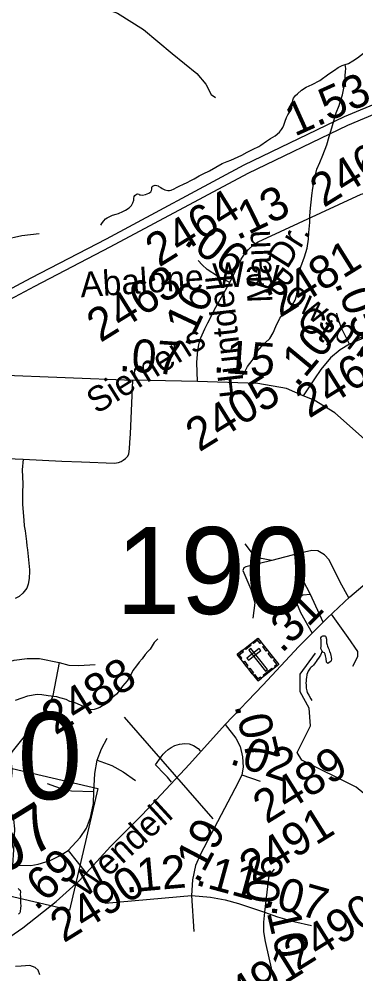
# Model space of a CAD drawing. Extents: x 2001466 to 31450019, y -30647475 to 847247.
# Drawn here: x 2179202 to 2181740, y 748208 to 755417 of the extents above; entities that cross this region are included whole.
import ezdxf

# ---------------------------------------------------------------- set-up
doc = ezdxf.new("R2010")
doc.units = 0
for name, color, linetype in [('Exist Cultural Cemetery CELL', 7, 'Continuous'), ('Exist Hydrographic Creek Single Shore', 7, 'Continuous'), ('Exist Hydrographic Misc Water Feature', 7, 'Continuous'), ('Exist Road Non-System Type 51', 7, 'Continuous'), ('Exist Road Primary NC Attributed', 7, 'Continuous'), ('Exist Road Primary NC Label', 7, 'Continuous'), ('Exist Road Primary NC Service Mileage Hundredths English Label', 7, 'Continuous'), ('Exist Road Primary NC Shield CELL', 7, 'Continuous'), ('Exist Road Primary NC Shield Number Label', 7, 'Continuous'), ('Exist Road Primary US Divided Attributed', 7, 'Continuous'), ('Exist Road Primary US Mileage Hundredths English Label', 7, 'Continuous'), ('Exist Road Secondary Mileage Hundredths English Label', 7, 'Continuous'), ('Exist Road Secondary Structure Standard Bridge Number Label', 7, 'Continuous'), ('Exist Road Secondary Type 51 Attributed', 7, 'Continuous'), ('Exist Road Secondary Type 51 Label', 7, 'Continuous'), ('Exist Road Secondary Type 51 Number Label', 7, 'Continuous')]:
    doc.layers.add(name, color=color, linetype=linetype)

msp = doc.modelspace()

# ---------------------------------------------------------------- linework, layer by layer
at = {"layer": 'Exist Cultural Cemetery CELL'}
for points in [[(2180845.5, 750619.4), (2181001.7, 750742.8), (2181159.5, 750543), (2181003.3, 750419.5)], [(2180903.6, 750665.2), (2180944.3, 750697.4), (2180951.3, 750688.4), (2180910.7, 750656.3)], [(2181028.6, 750708.8), (2181019.7, 750701.7), (2180999.8, 750727), (2180967.9, 750701.9), (2180961, 750710.6), (2181001.8, 750742.8)], [(2181065, 750644.4), (2181038.1, 750678.3), (2181047.1, 750685.4), (2181073.9, 750651.4)], [(2180872.3, 750585.4), (2180881.2, 750592.4), (2180861.3, 750617.7), (2180893.1, 750642.8), (2180886.2, 750651.5), (2180845.5, 750619.4)], [(2180919.7, 750591.2), (2180931.3, 750576.6), (2181023.7, 750649.6), (2181012.1, 750664.2)], [(2180949.2, 750663.9), (2180934.5, 750652.4), (2181060.2, 750493.2), (2181074.9, 750504.8)], [(2181105.8, 750592.6), (2181079, 750626.6), (2181087.9, 750633.7), (2181114.8, 750599.7)], [(2180918.3, 750527.2), (2180891.4, 750561.1), (2180900.4, 750568.2), (2180927.2, 750534.2)], [(2181133.5, 750522.4), (2181126.4, 750531.4), (2181143.7, 750545.1), (2181118.6, 750576.8), (2181127.4, 750583.7), (2181159.5, 750543)], [(2180959.9, 750474.4), (2180933.1, 750508.4), (2180942, 750515.4), (2180968.9, 750481.5)], [(2181029.2, 750440.1), (2181022.1, 750449.1), (2181004.9, 750435.5), (2180979.8, 750467.2), (2180971.1, 750460.3), (2181003.2, 750419.5)], [(2181041.3, 750464.2), (2181107.9, 750516.8), (2181114.9, 750507.8), (2181048.4, 750455.2)]]:
    msp.add_lwpolyline(points, close=True, dxfattribs=at)
at = {"layer": 'Exist Hydrographic Creek Single Shore'}
msp.add_lwpolyline([(2183862.9, 748759.6), (2183595.9, 748784.7), (2183229.9, 748723.3), (2182980, 748715.3), (2182755, 748756.1), (2182328.9, 748994.5), (2182043.1, 749367.7), (2181742.1, 749616.6), (2181333, 749821.8), (2181299, 749878.2), (2181398, 750079.6), (2181389, 750214.3), (2181321.1, 750337.1), (2181321.1, 750471.6), (2181435.9, 750630)], dxfattribs=at)
at = {"layer": 'Exist Hydrographic Misc Water Feature'}
for points in [[(2181660.3, 755073.2), (2181684, 755081.4), (2181718.1, 755101.4), (2181751.9, 755123.9), (2181821.4, 755176.3), (2181888.9, 755234.6), (2181924.6, 755272.6), (2181948.6, 755306.7), (2181970.5, 755337.1), (2181980.5, 755351)], [(2180869.4, 752707.8), (2180895.2, 752737.9), (2180924.9, 752793.9), (2180958.8, 752838.3), (2180974.4, 752866.3), (2180996.5, 752906.4), (2181046.1, 752964.6), (2181052.3, 752968.5), (2181055.8, 752972.4), (2181091.8, 753004.7), (2181117.5, 753046.7), (2181137.4, 753096.8), (2181166.9, 753157.3), (2181190.5, 753189.4), (2181218.8, 753213.5), (2181248.3, 753237.5), (2181266.1, 753263.5), (2181284, 753293.7), (2181294, 753327.9), (2181297.7, 753355.7), (2181303.5, 753406), (2181307.4, 753443.9), (2181313.3, 753497.8), (2181326.8, 753546.1), (2181354.3, 753622.2), (2181374, 753688.2), (2181383.4, 753756.1), (2181387.1, 753806.3), (2181392.7, 753880.1), (2181394.7, 753930.1), (2181398.2, 753990), (2181405.8, 754056.2), (2181407.6, 754084.3), (2181415.2, 754140.3), (2181429, 754210.1), (2181446.6, 754282.4), (2181468.3, 754334.3), (2181491.7, 754390.5), (2181521.4, 754466.7), (2181539.3, 754530.9), (2181559, 754594.9), (2181580.3, 754665.1), (2181592, 754709.2), (2181613.7, 754763), (2181625.6, 754799), (2181639.1, 754845.2), (2181652.9, 754907.2), (2181658.6, 754949.3), (2181660.5, 754991.3), (2181662.3, 755019.4), (2181664.6, 755043.4), (2181660.3, 755073.2)], [(2181277.4, 754829.3), (2181285.6, 754839.4), (2181301, 754853.3), (2181331.3, 754879.6), (2181366.8, 754901.8), (2181411.1, 754921.9), (2181468.7, 754954.1), (2181536.6, 755002.7), (2181580.5, 755030.9), (2181608, 755051.1), (2181638.1, 755065.2), (2181660.3, 755073.2)], [(2179819.5, 753859.5), (2179825, 753873.2), (2179831.2, 753881.3), (2179841.2, 753893.5), (2179853.3, 753907.5), (2179864.8, 753915.5), (2179881, 753923.6), (2179906.9, 753935.9), (2179932.9, 753943.8), (2179950.9, 753950), (2179984.8, 753964.3), (2180004.7, 753974.3), (2180032.3, 753992.4), (2180048.5, 754008.6), (2180058.6, 754030.6), (2180066.4, 754048.5), (2180068.2, 754062.8), (2180070.3, 754076.7), (2180074, 754084.7), (2180088.1, 754094.7), (2180093.9, 754096.7), (2180104.1, 754094.7), (2180109.9, 754091), (2180116, 754088.9), (2180131.8, 754086.9), (2180155.8, 754093), (2180180, 754103.1), (2180193.9, 754113.2), (2180199.9, 754123.2), (2180201.7, 754131.5), (2180201.7, 754147.3), (2180205.8, 754153.2), (2180212, 754157.5), (2180219.6, 754159.2), (2180227.6, 754161.7), (2180239.4, 754159.5), (2180249.3, 754157.6), (2180256.1, 754153.7), (2180269.6, 754143.9), (2180281.7, 754137.6), (2180301.8, 754128.1), (2180322.1, 754121.8), (2180335.6, 754122.2), (2180347.5, 754124), (2180370.1, 754134.5), (2180389.5, 754144.4), (2180413.7, 754156.6), (2180437.3, 754168.9), (2180473.6, 754184.9), (2180491, 754194.8), (2180521.4, 754210.9), (2180559.1, 754233.2), (2180588.9, 754249.4), (2180636.8, 754271.8), (2180684.8, 754299.8), (2180732.6, 754326.3), (2180770.5, 754342.4), (2180798.2, 754352.5), (2180882.1, 754388.9), (2180921.9, 754411.3), (2180965.7, 754435.4), (2181010, 754455.9), (2181023.8, 754464), (2181067.2, 754496), (2181097.2, 754514.2), (2181133.1, 754536.3), (2181165.1, 754562.7), (2181181, 754582.6), (2181190.7, 754598.6), (2181196.6, 754614.7), (2181208.5, 754647), (2181218.8, 754673.1), (2181228.4, 754693.1), (2181232.3, 754701), (2181249.7, 754727.2), (2181257.9, 754745), (2181259.8, 754769.1), (2181261.8, 754789), (2181265.3, 754805.1), (2181271.5, 754819.2), (2181277.4, 754829.3)], [(2181487, 750643.7), (2181476.7, 750663.5), (2181478.8, 750681.5), (2181478.8, 750695.7), (2181478.6, 750707.9), (2181478.4, 750729.8), (2181476.3, 750737.9), (2181476.5, 750741.5), (2181476.3, 750745.6), (2181480.2, 750753.5), (2181486.2, 750757.9), (2181490.3, 750759.7), (2181496.2, 750759.6), (2181500.3, 750759.8), (2181506.3, 750759.7), (2181510.4, 750757.9), (2181514.5, 750752), (2181518.6, 750735.9), (2181520.2, 750725.9), (2181520.2, 750708.1), (2181524.9, 750692), (2181527, 750681.9), (2181530.5, 750670), (2181532.9, 750664), (2181538.5, 750654.2), (2181540.9, 750640.1), (2181547.1, 750633.9), (2181551, 750612.2), (2181553.2, 750602.1), (2181555.3, 750596.1), (2181557.3, 750584), (2181555.3, 750574.2), (2181551.2, 750566.3), (2181539.5, 750557.9), (2181529.2, 750550.1), (2181523.5, 750555.9), (2181519.8, 750561.7), (2181515.5, 750590), (2181510.8, 750608.1), (2181508.9, 750621.8), (2181503, 750632), (2181491.1, 750637.9), (2181487, 750643.7)], [(2180246.6, 750736.7), (2180220.8, 750708.5), (2180205.4, 750684.6), (2180189.4, 750660.6), (2180173.2, 750642.4), (2180151.3, 750618.1), (2180129.7, 750586), (2180108, 750560.1), (2180085.9, 750533.8), (2180060.2, 750499.6), (2180040.8, 750461.6), (2180016.8, 750419.4), (2179982.7, 750379.4), (2179951.6, 750337.1), (2179935.4, 750320.9), (2179907.5, 750296.7), (2179883.7, 750268.7), (2179867.7, 750256.9), (2179850.1, 750242.6), (2179829.8, 750230.6), (2179810.3, 750218.5), (2179791.8, 750210.4), (2179768, 750204.2), (2179742, 750202.1), (2179715.9, 750213.7), (2179693.8, 750224), (2179665.7, 750235.5), (2179623.9, 750255.2), (2179585.5, 750265.1), (2179556, 750278.9), (2179519.3, 750288.9), (2179509.5, 750292.8), (2179487.3, 750300.6), (2179421.5, 750306.1), (2179373.5, 750313.8), (2179339.3, 750317.7), (2179265.4, 750305.4), (2179223.6, 750289), (2179173.8, 750273)], [(2181487, 750643.7), (2181473, 750613.8), (2181459.3, 750591.6), (2181449.3, 750579.7), (2181441.3, 750567.5), (2181433.7, 750555.3), (2181421.6, 750539.2), (2181411.5, 750527.4), (2181403.7, 750523.3), (2181395.5, 750515.2), (2181381.6, 750493.3), (2181371.7, 750467.2), (2181371.9, 750463.2), (2181368.1, 750449.2), (2181366.2, 750431.2), (2181366.4, 750419), (2181364, 750405.2), (2181366.4, 750386.9), (2181366.2, 750365.1), (2181370.7, 750345.3), (2181373, 750331.2), (2181386.7, 750311.3), (2181401.1, 750285.2), (2181408.9, 750271.4)], [(2179195.9, 748851.4), (2179203.7, 748845.4), (2179209.7, 748839.6), (2179211.9, 748825.5), (2179210.1, 748809.6), (2179212.1, 748785.7), (2179212.1, 748765.4), (2179212.5, 748741.5), (2179214.6, 748721.6), (2179213, 748703.6), (2179210.7, 748679.7), (2179206.8, 748669.7), (2179197.2, 748659.4)]]:
    msp.add_lwpolyline(points, dxfattribs=at)
at = {"layer": 'Exist Road Non-System Type 51'}
for p, q in [((2178826.5, 752737.5), (2180060.2, 752690.6)), ((2181399.7, 751071.3), (2181317.3, 751226.5)), ((2181493.4, 750864.3), (2181399.7, 751071.3))]:
    msp.add_line(p, q, dxfattribs=at)
for points in [[(2179499.4, 755556.6), (2179660.8, 755545.4), (2179779.6, 755523), (2179943.2, 755462.5), (2180140.4, 755336.9), (2180355.6, 755157.5), (2180541.6, 755005), (2180608.8, 754924.2), (2180649.1, 754848.4), (2180682.8, 754823.8)], [(2178182.5, 753635.7), (2178336.2, 753576.7), (2178464.5, 753527.5), (2178560.1, 753505.7), (2178636.5, 753514.4), (2178939.6, 753680.5), (2179089.8, 753751.6), (2179223.6, 753781.6), (2179354.6, 753798)], [(2179231.9, 752094.4), (2179525.3, 752079.2), (2179673, 752073.6), (2179920.8, 752064.5), (2179952.1, 752069.5), (2179971.8, 752075.7), (2179987.2, 752085.2), (2180003.3, 752098.8), (2180020.6, 752115.5), (2180030, 752134.3), (2180034.8, 752172.2), (2180037.6, 752220.1), (2180042.7, 752284.2), (2180060.2, 752690.6)], [(2178814.7, 752615.7), (2178794.9, 752209.4), (2178795.4, 752192.6), (2178796.5, 752181), (2178800.3, 752169.1), (2178804.1, 752161), (2178809.9, 752149.1), (2178815.9, 752142), (2178826.5, 752132.7), (2178840.7, 752122.7), (2178850.2, 752117.7), (2178864.1, 752113.8), (2178883.5, 752111), (2178908.2, 752108.1), (2178929.2, 752106.8), (2179231.9, 752094.4)], [(2179231.9, 752094.4), (2179226.6, 752012.6), (2179231, 751906.7), (2179229.1, 751840.7), (2179227.2, 751814.8), (2179227, 751750.8), (2179236.8, 751632.2), (2179240.9, 751590.7), (2179247, 751552.6), (2179256.9, 751472.6), (2179261.1, 751440.5), (2179265, 751408.6), (2179280.9, 751258.5), (2179281, 751230.5), (2179278.9, 751210.6), (2179277, 751192.6), (2179270.9, 751150.5), (2179260.9, 751120.6), (2179230.9, 751082.6), (2179202.8, 751056.6), (2179173.7, 751042.3)], [(2181106, 751328.6), (2181014, 751347.1), (2180953.2, 751392.7), (2180905.2, 751455.7)], [(2181686.2, 751046), (2181622.4, 751165.8), (2181538.9, 751334.2), (2181503.5, 751372.5), (2181452.6, 751400.8), (2181407.3, 751403.6), (2181308.3, 751382.4), (2181106, 751328.6)], [(2181106, 751328.6), (2180912.2, 751280.4), (2180895.2, 751273.4), (2180889.6, 751253.5), (2180948.8, 751111.3), (2180977.9, 751009.5), (2180963.4, 750893.1)], [(2181399.7, 751071.3), (2181341.5, 751066.5), (2181302.7, 751042.2), (2181293, 751008.3), (2181322.1, 750935.5), (2181410.7, 750781.3)], [(2181554.4, 750923.1), (2181680.9, 750747.6), (2181753.6, 750640.9)], [(2181753.6, 750640.9), (2181753.6, 750602.1), (2181714.8, 750529.3)], [(2178709.8, 750011.3), (2178791.4, 750116.9), (2178837, 750203.4), (2178880.2, 750321.1), (2178923.4, 750429.2), (2178988.2, 750501.2), (2179086.6, 750554.1), (2179165.9, 750575.7), (2179261.9, 750590.1), (2179355.5, 750590.1), (2179504.3, 750558.9)], [(2179504.3, 750558.9), (2179456.3, 750309.1), (2179441.9, 750265.9), (2179410.7, 750213), (2179149.1, 749886.4), (2179108.2, 749816.7), (2179084.2, 749751.9), (2179077, 749675), (2179081.8, 749598.1), (2179108.2, 749514.6), (2179161.1, 749372.9), (2179168.3, 749303.2), (2179161.1, 749144.7), (2179151.5, 749029.4)], [(2179504.3, 750558.9), (2179576.3, 750539.7), (2179653.1, 750534.9), (2179775.5, 750544.5)], [(2179791.8, 749821.3), (2179823, 749907.7), (2179866.2, 749987)], [(2180229.6, 749786.7), (2180272.6, 749846.8), (2180288.6, 749865.6), (2180302.9, 749880.9), (2180326.8, 749902.8), (2180348.6, 749916.8), (2180375.4, 749932), (2180410.8, 749942.7), (2180452, 749946.9), (2180484, 749943.8), (2180516.7, 749932.7), (2180552.3, 749910.4), (2180568.1, 749892.3)], [(2179765.4, 749583.3), (2179772.6, 749720.4), (2179791.8, 749821.3)], [(2179791.8, 749821.3), (2179902.2, 749780.4), (2179986.2, 749732.4), (2180079.9, 749667.6)], [(2180351.1, 749654.4), (2180320.6, 749692.8), (2180278.6, 749736.9), (2180250.5, 749764.8), (2180229.6, 749786.7)], [(2179765.4, 749583.3), (2179597.4, 749588.1), (2179542.2, 749597.7), (2179417.4, 749643.3)], [(2179571.5, 749139.9), (2179662.2, 749237.4), (2179710.2, 749307), (2179741.4, 749388.7), (2179763, 749494.4), (2179765.4, 749583.3)], [(2179151.5, 749029.4), (2179290.7, 749027), (2179345.9, 749036.6), (2179437.1, 749063), (2179506.7, 749099), (2179571.5, 749139.9)], [(2179571.5, 749139.9), (2179707.5, 748968.6)], [(2180502.7, 748799.6), (2180518.6, 748527.3)], [(2179358.3, 748199.4), (2179346.4, 748234.9), (2179322.8, 748255.2), (2179282.2, 748272.2), (2179217.9, 748267.1), (2179173.9, 748263.7)]]:
    msp.add_lwpolyline(points, dxfattribs=at)
at = {"layer": 'Exist Road Primary NC Attributed'}
for points in [[(2180755.9, 750091), (2181039.7, 750386.7), (2181309.6, 750679.9), (2181523.6, 750894.6), (2181695.2, 751053.7), (2181909.2, 751237)], [(2177992.6, 747753.2), (2178191.4, 747896.6), (2178415.3, 748037), (2178591.1, 748139.6), (2178860.1, 748309.2), (2179073.5, 748447.4), (2179230.5, 748556.3), (2179482.7, 748753.2), (2179656.4, 748912.4), (2179890.7, 749169.9), (2180129.8, 749408.7), (2180486.1, 749791.9), (2180755.9, 750091)]]:
    msp.add_lwpolyline(points, dxfattribs=at)
at = {"layer": 'Exist Road Primary NC Shield CELL'}
msp.add_lwpolyline([(2178665.5, 748903.2), (2178878.7, 749820.6), (2179796.1, 749607.4), (2179582.9, 748690)], close=True, dxfattribs=at)
at = {"layer": 'Exist Road Primary US Divided Attributed'}
for points in [[(2184342.9, 755525.5), (2183498.3, 755316.3), (2182865.1, 755145.4), (2182188.8, 754901.6), (2181651.7, 754678.1), (2180897.2, 754312.8), (2179857.2, 753755.9), (2179289.5, 753460.8), (2178493.6, 753035.9), (2178148.4, 752839.7), (2177995.1, 752736.9)], [(2177992.8, 752657.4), (2178181.8, 752781.1), (2178526.2, 752976.8), (2179320.9, 753401.2), (2179888.6, 753696.2), (2180927.8, 754252.7), (2181679.4, 754616.6), (2182213.2, 754838.8), (2182885.3, 755081), (2183515.2, 755251), (2184057.3, 755385.1)]]:
    msp.add_lwpolyline(points, dxfattribs=at)
at = {"layer": 'Exist Road Secondary Type 51 Attributed'}
for points in [[(2180789.4, 753427), (2180876.1, 753603.1), (2180901.2, 753641.4), (2180931.4, 753678.1), (2180968.8, 753711.3), (2181004.9, 753735), (2181780.2, 754095.8), (2181856, 754115.8), (2181941.1, 754117.1), (2182015.5, 754098.5), (2182089.3, 754056.2), (2182146.5, 753999.1), (2182194.3, 753920.7), (2182242.2, 753771.9), (2182288.5, 753547.9), (2182293.8, 753472.2), (2182285.8, 753387.2), (2182258, 753308), (2182211.5, 753232.3), (2182176.9, 753187.1)], [(2180789.4, 753427), (2180698.8, 753476.8), (2180618.8, 753525.7), (2180581, 753560), (2180552.4, 753593.3)], [(2180547.3, 752679.2), (2180542.9, 752825), (2180549.2, 752917.2), (2180558.9, 752968.7), (2180571.6, 753011.1), (2180603, 753078.7), (2180625.5, 753123.8), (2180685.9, 753241.4), (2180789.4, 753427)], [(2181692.7, 752961.6), (2181636.2, 753073.5), (2181608.8, 753143.5), (2181596.9, 753196.6)], [(2182176.9, 753187.1), (2182118.4, 753129), (2182072.2, 753099.7), (2182024.1, 753078.2), (2181917.4, 753045), (2181799.1, 753007.3), (2181732.2, 752979.9), (2181692.7, 752961.6)], [(2181692.7, 752961.6), (2181622.7, 752919), (2181549.8, 752858.2), (2181476.8, 752769.9), (2181428.1, 752699.9), (2181342.9, 752573.4)], [(2180547.3, 752679.2), (2180064.4, 752691.4)], [(2181342.9, 752573.4), (2181216.5, 752626.5), (2181001, 752666.3), (2180547.3, 752679.2)], [(2182495.2, 751662.1), (2182293.2, 751843.3), (2181872.6, 752184.6), (2181580.7, 752444.3), (2181425.8, 752538.6), (2181342.9, 752573.4)], [(2180755.9, 750091), (2180836.6, 749988.7), (2180868.4, 749925.1), (2180887.2, 749845.5), (2180890.1, 749767.4), (2180880, 749709.5)], [(2180880, 749709.5), (2180854, 749653.1), (2180570.6, 749112.2), (2180531.6, 749025.4), (2180508.4, 748918.2), (2180502.7, 748799.6)], [(2180880, 749709.5), (2181020.2, 749663.2)], [(2181125.7, 748999.2), (2181095.4, 748960.2), (2181080.9, 748934.1), (2181050.6, 748673.7)], [(2179851.2, 748742.2), (2180502.7, 748799.6)], [(2180502.7, 748799.6), (2180644.3, 748786.6), (2180755.6, 748767.8), (2180856.8, 748740.3), (2181050.6, 748673.7)], [(2181050.6, 748673.7), (2181043.3, 748598.8), (2181043.3, 748525), (2181056.3, 748451.2), (2181130.1, 748128)], [(2181050.6, 748673.7), (2181148.9, 748639), (2181271.8, 748604.3), (2181406.2, 748573.9)]]:
    msp.add_lwpolyline(points, dxfattribs=at)
at = {"layer": 'Exist Road Secondary Type 51 Number Label'}
msp.add_line((2180664.3, 749377.3), (2179996.8, 750145.6), dxfattribs=at)

# ---------------------------------------------------------------- texts
at = {"layer": 'Exist Road Primary NC Label'}
msp.add_text('Wendell', height=190, rotation=42.5228, dxfattribs=at).set_placement((2179697.4, 748772.5))
at = {"layer": 'Exist Road Primary NC Service Mileage Hundredths English Label'}
for s, rotation, p in [('.31', 45.09023, (2181183.3, 750622.9)), ('.69', 42.49942, (2179329, 748679.1))]:
    msp.add_text(s, height=250, rotation=rotation, dxfattribs=at).set_placement(p)
at = {"layer": 'Exist Road Primary NC Shield Number Label'}
msp.add_text('97', height=350, rotation=31.91803, dxfattribs=at).set_placement((2179078, 748948.7))
at = {"layer": 'Exist Road Primary US Mileage Hundredths English Label'}
msp.add_text('1.53', height=250, rotation=24.22568, dxfattribs=at).set_placement((2181278.9, 754527.4))
at = {"layer": 'Exist Road Secondary Mileage Hundredths English Label'}
for s, rotation, p in [('.13', 26.23467, (2180846.1, 753744.2)), ('.06', 324.35833, (2180434.2, 753726.6)), ('.16', 64.82615, (2180478.4, 752931.5)), ('.05', 291.35733, (2181577.9, 753421.7)), ('.10', 50.4085, (2181296.2, 752628.8)), ('.07', 355.9022, (2179950.7, 752760.9)), ('.15', 355.9022, (2180659.6, 752750.4)), ('.07', 283.28966, (2180823.6, 750232.7)), ('.02', 341.73129, (2180780.4, 749796.1)), ('.19', 62.3521, (2180550.9, 748881.4)), ('.12', 5.0384, (2180005.9, 748820.4)), ('.06', 83.35004, (2181141.5, 748634.9)), ('.11', 344.80427, (2180522.7, 748881.5)), ('.07', 344.22259, (2181040.6, 748729)), ('.10', 282.85136, (2181047.2, 748763.6))]:
    msp.add_text(s, height=250, rotation=rotation, dxfattribs=at).set_placement(p)
at = {"layer": 'Exist Road Secondary Structure Standard Bridge Number Label'}
for s, p in [('190', (2179930, 750924.7)), ('150', (2178214.3, 749526.8))]:
    msp.add_text(s, height=656.17, dxfattribs=at).set_placement(p)
at = {"layer": 'Exist Road Secondary Type 51 Label'}
for s, rotation, p in [('Main', 92.1192, (2181112.6, 753276.8)), ('Dr.', 57.85076, (2181223.5, 753522.3)), ('Abalone Way', 3.77968, (2179668.1, 753315.9)), ('Bowsprit', 322.58634, (2181056.8, 753406.4)), ('Huntdell', 96.38291, (2180905.8, 752567.5)), ('Ct.', 327.48891, (2181282.1, 753108.1)), ('Siemens', 31.98192, (2179786.9, 752430.9))]:
    msp.add_text(s, height=190, rotation=rotation, dxfattribs=at).set_placement(p)
at = {"layer": 'Exist Road Secondary Type 51 Number Label'}
for s, p in [('2463', (2181498, 753989.8)), ('2464', (2180257.2, 753539.3)), ('2481', (2181169.6, 753159.2)), ('2463', (2179815, 752970.2)), ('2463', (2181387.7, 752398.4)), ('2405', (2180560.2, 752144.1)), ('2488', (2179474.7, 750006.6)), ('2489', (2181067.7, 749335.4)), ('2491', (2180965.2, 748879.6)), ('2490', (2179538.7, 748437.8)), ('2490', (2181300.1, 748225)), ('2491', (2180729.1, 747830.9))]:
    msp.add_text(s, height=250, rotation=31.91803, dxfattribs=at).set_placement(p)

doc.saveas('drawing.dxf')
